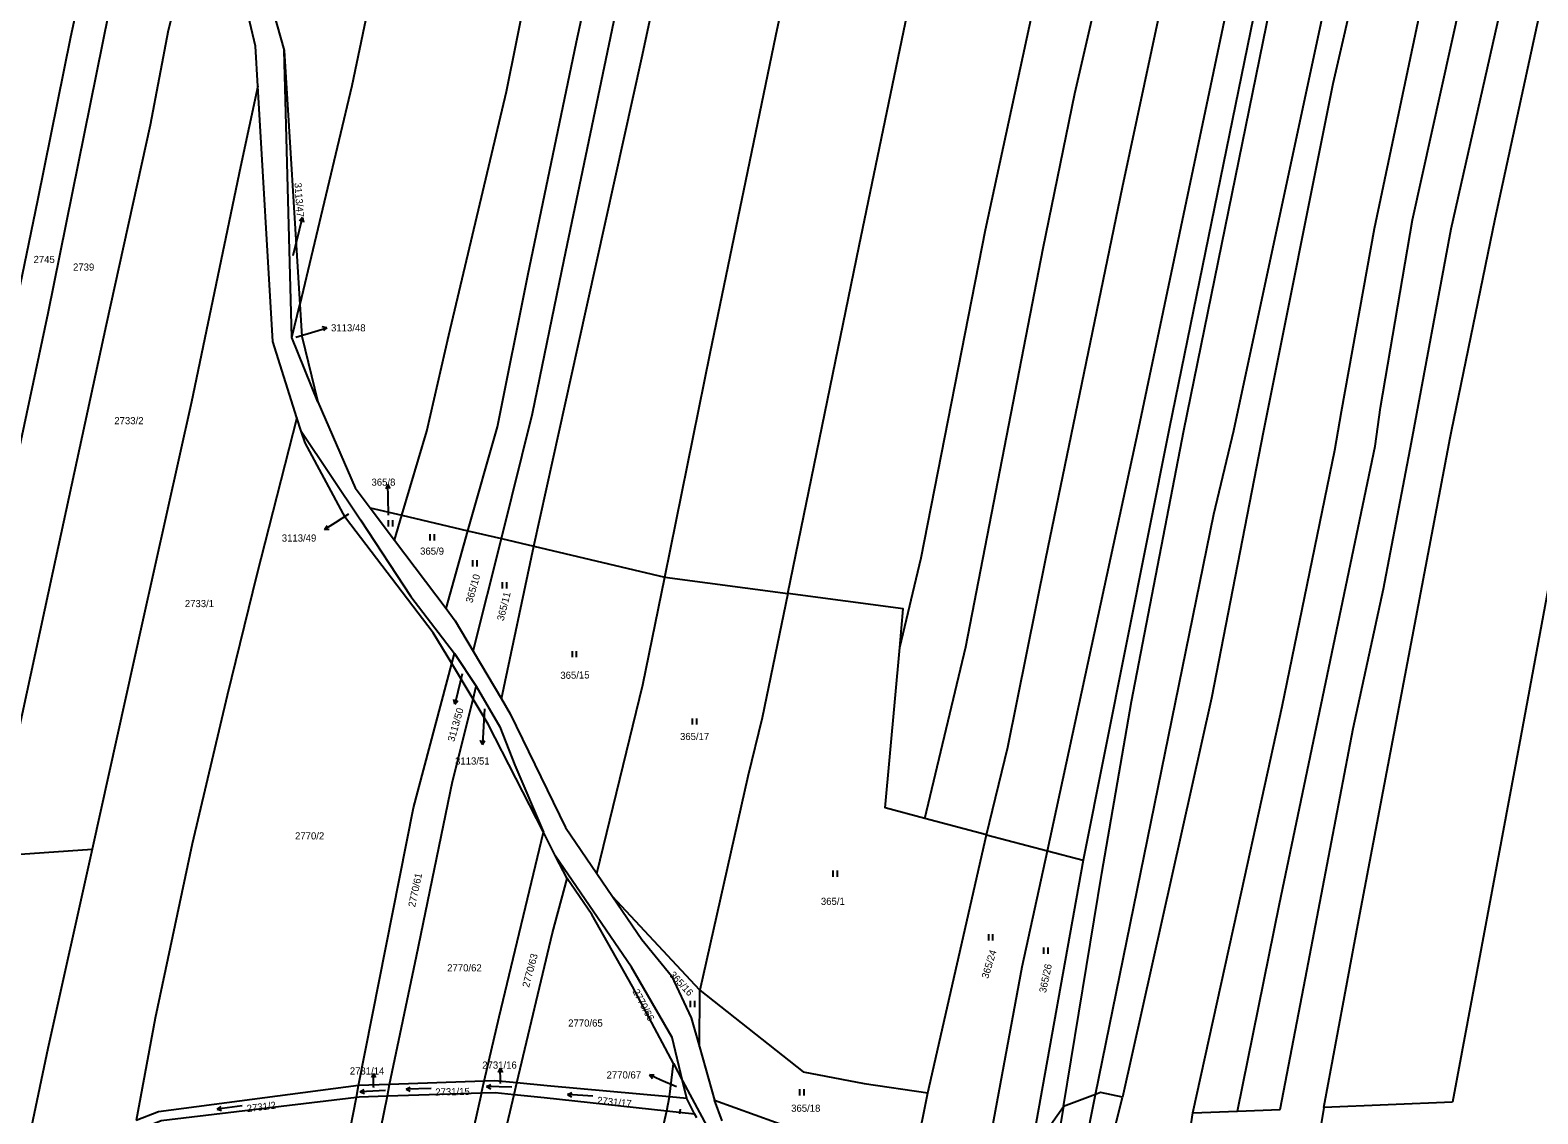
# Model space of a CAD drawing. Extents: x -755528 to -748832, y -1118122 to -1111095.
# Drawn here: x -753634.1 to -753275.1, y -1114927.7 to -1114669.7 of the extents above; entities that cross this region are included whole.
import ezdxf

# ---------------------------------------------------------------- set-up
doc = ezdxf.new("R2010")
doc.units = 0
for name, color, linetype in [('DZ_DO_PUPFL', 7, 'Continuous'), ('DZ_NAD_ZPF', 7, 'Continuous'), ('legenda barvy', 7, 'Continuous'), ('TZ_UMVŽST', 7, 'Continuous')]:
    doc.layers.add(name, color=color, linetype=linetype)

msp = doc.modelspace()

# ---------------------------------------------------------------- linework, layer by layer
at = {"layer": 'DZ_NAD_ZPF'}
for p, q in [((-753577.47, -1114661.02), (-753573.61, -1114674.53)), ((-753571.78, -1114742.92), (-753573.61, -1114674.53)), ((-753573.61, -1114674.53), (-753569.89, -1114734.99)), ((-753571.78, -1114742.92), (-753569.89, -1114734.99)), ((-753565.61, -1114758.21), (-753571.78, -1114742.92)), ((-753569.56, -1114765.17), (-753570.58, -1114761.97)), ((-753553.18, -1114783.41), (-753547.36, -1114791.13)), ((-753553.18, -1114783.41), (-753545.64, -1114785.18)), ((-753547.36, -1114791.13), (-753545.64, -1114785.18)), ((-753545.64, -1114785.18), (-753529.9, -1114788.88)), ((-753535.09, -1114807.4), (-753529.9, -1114788.88)), ((-753529.9, -1114788.88), (-753521.92, -1114790.76)), ((-753547.36, -1114791.13), (-753535.09, -1114807.4)), ((-753528.59, -1114817.59), (-753521.92, -1114790.76)), ((-753521.92, -1114790.76), (-753514.21, -1114792.57)), ((-753521.89, -1114828.92), (-753514.21, -1114792.57)), ((-753514.21, -1114792.57), (-753482.99, -1114799.91)), ((-753482.99, -1114799.91), (-753453.67, -1114803.81)), ((-753528.59, -1114817.59), (-753521.89, -1114828.92)), ((-753533.71, -1114820.53), (-753533.08, -1114818.09)), ((-753528.6, -1114829.01), (-753533.71, -1114820.53)), ((-753533.08, -1114818.09), (-753527.92, -1114825.93)), ((-753528.6, -1114829.01), (-753527.92, -1114825.93)), ((-753509, -1114866.34), (-753511.91, -1114860.63)), ((-753406.39, -1114861.26), (-753421.05, -1114857.37)), ((-753420.37, -1114922.71), (-753406.39, -1114861.26)), ((-753406.39, -1114861.26), (-753391.91, -1114865.1)), ((-753643.43, -1114866.36), (-753619.35, -1114864.71)), ((-753506.27, -1114871.68), (-753509, -1114866.34)), ((-753383.41, -1114867.35), (-753395.87, -1114937.08)), ((-753391.91, -1114865.1), (-753383.41, -1114867.35)), ((-753499.16, -1114870.52), (-753495.47, -1114875.94)), ((-753474.62, -1114898.28), (-753495.47, -1114875.94)), ((-753474.74, -1114911.76), (-753474.62, -1114898.28)), ((-753474.74, -1114911.76), (-753471.13, -1114924.44)), ((-753481.87, -1114923.69), (-753480.96, -1114915.73)), ((-753480.96, -1114915.73), (-753478.76, -1114919.85)), ((-753556.37, -1114923.73), (-753555.92, -1114921.01)), ((-753548.52, -1114920.75), (-753555.92, -1114921.01)), ((-753549.06, -1114923.44), (-753548.52, -1114920.75)), ((-753526.02, -1114919.98), (-753548.52, -1114920.75)), ((-753526.67, -1114922.71), (-753526.02, -1114919.98)), ((-753518.89, -1114923.09), (-753518.24, -1114920.37)), ((-753477.73, -1114924.07), (-753478.76, -1114919.85)), ((-753549.06, -1114923.44), (-753526.67, -1114922.71)), ((-753482.54, -1114926.98), (-753481.87, -1114923.69)), ((-753477.73, -1114924.07), (-753481.87, -1114923.69)), ((-753475.9, -1114927.69), (-753477.73, -1114924.07)), ((-753469.35, -1114929.4), (-753471.13, -1114924.44)), ((-753471.13, -1114924.44), (-753451.81, -1114931.44)), ((-753380.47, -1114923.09), (-753388.04, -1114925.99)), ((-753386.18, -1114952.09), (-753380.47, -1114923.09)), ((-753380.97, -1114951.65), (-753374.05, -1114923.78)), ((-753295.48, -1114924.98), (-753326.11, -1114926.23)), ((-753482.54, -1114926.98), (-753475.9, -1114927.69)), ((-753475.39, -1114928.71), (-753475.9, -1114927.69)), ((-753388.04, -1114925.99), (-753392.57, -1114952.63)), ((-753391.05, -1114930.25), (-753388.04, -1114925.99)), ((-753360.79, -1114949.94), (-753357.27, -1114927.51)), ((-753357.27, -1114927.51), (-753346.62, -1114927.07)), ((-753346.62, -1114927.07), (-753336.49, -1114926.66)), ((-753326.11, -1114926.23), (-753329.47, -1114947.29))]:
    msp.add_line(p, q, dxfattribs=at)
for points in [[(-753391.91, -1114865.1), (-753370.12, -1114764.37), (-753342.59, -1114633.36), (-753322.4, -1114540.31), (-753310.19, -1114487.69), (-753300.09, -1114436.67), (-753286.77, -1114370.72), (-753264.8, -1114264.8), (-753262.01, -1114250.34)], [(-753388.04, -1114925.99), (-753378.91, -1114870.41), (-753371.84, -1114829.51), (-753359.4, -1114765.02), (-753333.11, -1114636.17), (-753306.83, -1114507.39), (-753280.51, -1114378.41), (-753254.07, -1114248.85)], [(-753257.43, -1114249.32), (-753283.85, -1114378.41), (-753310.17, -1114506.98), (-753336.45, -1114635.37), (-753362.83, -1114764.23), (-753383.41, -1114867.35)], [(-753380.47, -1114923.09), (-753352.25, -1114784.92), (-753347.52, -1114765.05), (-753321.73, -1114644.54), (-753301.78, -1114549.55), (-753285.73, -1114476.91), (-753267.23, -1114386.09), (-753258.53, -1114337.83), (-753251.49, -1114312.57), (-753241.68, -1114263.95)], [(-753406.39, -1114861.26), (-753401.29, -1114840.44), (-753392.31, -1114795.48), (-753374.02, -1114707.08), (-753358.06, -1114632.36), (-753344.31, -1114570.05), (-753328.24, -1114502.3), (-753313.96, -1114433.37), (-753295.87, -1114339.69), (-753280.83, -1114267.93)], [(-753235.13, -1114267.34), (-753240.39, -1114297.28), (-753251.09, -1114341.31), (-753268.66, -1114432.14), (-753285.44, -1114506.75), (-753288.02, -1114520.6), (-753301.19, -1114583.62), (-753323.96, -1114682.47), (-753340.43, -1114765.07), (-753352.84, -1114828.76), (-753374.05, -1114923.78)], [(-753357.27, -1114927.51), (-753345.65, -1114874.9), (-753335.97, -1114830.73), (-753323.45, -1114769.69), (-753321.88, -1114760.53), (-753313.99, -1114716.92), (-753301.83, -1114658.93), (-753285.34, -1114585.91), (-753271.38, -1114523.28), (-753269.62, -1114514.13), (-753252.93, -1114437.12), (-753248.23, -1114411.88), (-753236.35, -1114350.91), (-753218.84, -1114274.4)], [(-753421.05, -1114857.37), (-753411.32, -1114816.52), (-753392.9, -1114721.65), (-753385.36, -1114684.8), (-753362.12, -1114584), (-753347.03, -1114516.19), (-753330.1, -1114437.88), (-753316.74, -1114370.96), (-753298.04, -1114276.42)], [(-753346.62, -1114927.07), (-753336.64, -1114877.75), (-753313.83, -1114768.77), (-753312.59, -1114759.54), (-753304.99, -1114714.84), (-753288.84, -1114642.04), (-753280.2, -1114605.8), (-753261.79, -1114523.06), (-753246.79, -1114453.38), (-753233.8, -1114391.88), (-753226.71, -1114348.8), (-753209.38, -1114276.19)], [(-753336.49, -1114926.66), (-753330.42, -1114895.38), (-753319.07, -1114836), (-753311.85, -1114802.69), (-753305.21, -1114767.84), (-753295.75, -1114717.04), (-753281.21, -1114652.59), (-753269.65, -1114602.88), (-753259.3, -1114558.02), (-753248.82, -1114510.17), (-753229.75, -1114419.33), (-753218.76, -1114362.62), (-753210.75, -1114321.87), (-753200.23, -1114277.93)], [(-753482.99, -1114799.91), (-753472.19, -1114746.58), (-753456.54, -1114671.05), (-753443.54, -1114609.86), (-753429.02, -1114541.88), (-753415.04, -1114479.21), (-753399.63, -1114399.72), (-753389.17, -1114347.58), (-753374.92, -1114282.49)], [(-753326.11, -1114926.23), (-753317.74, -1114881.48), (-753296.03, -1114766.74), (-753295.7, -1114765.18), (-753285.26, -1114714.64), (-753270.38, -1114645.75), (-753262.54, -1114613.09), (-753253.99, -1114578.06), (-753242.92, -1114533.2), (-753229.75, -1114467.75), (-753214.48, -1114392.62), (-753201.31, -1114320.15), (-753191.66, -1114279.56)], [(-753427.05, -1114816.67), (-753421.95, -1114795.33), (-753406.63, -1114717.25), (-753393.37, -1114655.82), (-753363.47, -1114523.91), (-753342.5, -1114428.02), (-753332.6, -1114374.47), (-753323.21, -1114331.32), (-753312.67, -1114283.86)], [(-753453.67, -1114803.81), (-753436.75, -1114721.08), (-753422.62, -1114652.89), (-753404.93, -1114571.83), (-753384.78, -1114480.87), (-753376.55, -1114438.8), (-753364.34, -1114375.14), (-753354.33, -1114334.25), (-753342.84, -1114288.62)], [(-753521.92, -1114790.76), (-753514.51, -1114760.97), (-753506.94, -1114724.35), (-753491.12, -1114648.31), (-753472.33, -1114560.66), (-753460.31, -1114505.63), (-753447.2, -1114444.23), (-753434.61, -1114386.82), (-753422.98, -1114329.63), (-753416.75, -1114298.6), (-753415.43, -1114293.38)], [(-753514.21, -1114792.57), (-753503.61, -1114744.79), (-753488.31, -1114675.57), (-753468.49, -1114582.84), (-753445.47, -1114477.34), (-753425.56, -1114377.48), (-753408.97, -1114296.71), (-753408.09, -1114290.87)], [(-753529.9, -1114788.88), (-753522.81, -1114764.12), (-753515.64, -1114728.13), (-753504, -1114672.45), (-753489.29, -1114604.59), (-753479.49, -1114562.47), (-753466.97, -1114506.52), (-753458.84, -1114469.04), (-753446.41, -1114412.13), (-753439.28, -1114374.74), (-753424.14, -1114300.03)], [(-753545.64, -1114785.18), (-753539.64, -1114765.18), (-753534.46, -1114742.36), (-753520.67, -1114684.28), (-753515.99, -1114660.95), (-753492.74, -1114552.19), (-753480.23, -1114495.22), (-753460.74, -1114406.56), (-753455.16, -1114378.63), (-753439.66, -1114301.88)], [(-753477.67, -1114315.36), (-753482.48, -1114340.66), (-753489.85, -1114373.61), (-753501.24, -1114423.4), (-753519.79, -1114507.09), (-753533.42, -1114568.36), (-753549.84, -1114646.02), (-753557.48, -1114682.99), (-753569.89, -1114734.99)], [(-753610.25, -1114606.01), (-753617.12, -1114637.26), (-753624.49, -1114671.37), (-753632.34, -1114710.29), (-753639.7, -1114745.63), (-753646.59, -1114780.5), (-753654.58, -1114817.91), (-753663.71, -1114856.29), (-753671.41, -1114887.98), (-753679.86, -1114921.84)], [(-753604.79, -1114614.61), (-753613.99, -1114658.59), (-753629.87, -1114737.18), (-753640.64, -1114787.58), (-753650.44, -1114834.53), (-753663.46, -1114889.5), (-753671.97, -1114923.35)], [(-753592.96, -1114636.98), (-753601.26, -1114669.82), (-753605.55, -1114692.31), (-753616.04, -1114739.83), (-753628.68, -1114798.6), (-753643.43, -1114866.36)], [(-753579.89, -1114683.06), (-753580.44, -1114673.52), (-753583.19, -1114661.99), (-753589.7, -1114643.54), (-753592.96, -1114636.98)], [(-753579.89, -1114683.06), (-753584.03, -1114702.28), (-753595.68, -1114758.18), (-753607.42, -1114810.88), (-753619.35, -1114864.71)], [(-753570.58, -1114761.97), (-753576.36, -1114743.83), (-753579.89, -1114683.06)], [(-753569.89, -1114734.99), (-753569.42, -1114742.6), (-753565.61, -1114758.21)], [(-753565.61, -1114758.21), (-753556.7, -1114778.7), (-753553.18, -1114783.41)], [(-753570.58, -1114761.97), (-753580.11, -1114799.28), (-753587.21, -1114828.12), (-753595.54, -1114863.4), (-753604.34, -1114904.93), (-753608.87, -1114929.33)], [(-753533.71, -1114820.53), (-753538.12, -1114813.2), (-753559, -1114785.81), (-753568.66, -1114767.99), (-753569.56, -1114765.17)], [(-753569.56, -1114765.17), (-753555.44, -1114786.3), (-753543.49, -1114804.51), (-753533.08, -1114818.09)], [(-753265.56, -1114765.37), (-753267.16, -1114773.07), (-753279.16, -1114837.78), (-753295.48, -1114924.98)], [(-753499.16, -1114870.52), (-753488.21, -1114825.61), (-753482.99, -1114799.91)], [(-753453.67, -1114803.81), (-753459.79, -1114833.45), (-753463.25, -1114847.41), (-753474.62, -1114898.28)], [(-753427.05, -1114816.67), (-753426.22, -1114807.46), (-753453.67, -1114803.81)], [(-753535.09, -1114807.4), (-753532.88, -1114810.33), (-753528.59, -1114817.59)], [(-753421.05, -1114857.37), (-753430.49, -1114854.86), (-753427.05, -1114816.67)], [(-753555.92, -1114921.01), (-753542.87, -1114854.9), (-753533.71, -1114820.53)], [(-753527.92, -1114825.93), (-753522.24, -1114835.6), (-753518.74, -1114844.67), (-753511.91, -1114860.63)], [(-753548.52, -1114920.75), (-753542.13, -1114890.19), (-753533.55, -1114848.56), (-753528.6, -1114829.01)], [(-753511.91, -1114860.63), (-753525.05, -1114834.91), (-753528.6, -1114829.01)], [(-753521.89, -1114828.92), (-753519.79, -1114832.48), (-753506.65, -1114859.53), (-753499.16, -1114870.52)], [(-753526.02, -1114919.98), (-753522.41, -1114904.64), (-753511.91, -1114860.63)], [(-753619.35, -1114864.71), (-753629.9, -1114912.16), (-753637.4, -1114947.63)], [(-753478.76, -1114919.85), (-753481.26, -1114909.56), (-753490.91, -1114892.84), (-753509, -1114866.34)], [(-753408.1, -1114946.81), (-753405.08, -1114931.27), (-753397.93, -1114892.69), (-753391.91, -1114865.1)], [(-753518.24, -1114920.37), (-753509.77, -1114884.59), (-753506.27, -1114871.68)], [(-753480.96, -1114915.73), (-753490.68, -1114897.4), (-753500.41, -1114880.23), (-753506.27, -1114871.68)], [(-753495.47, -1114875.94), (-753488.46, -1114886.21), (-753481.4, -1114894.9), (-753476.69, -1114904.88), (-753474.74, -1114911.76)], [(-753474.62, -1114898.28), (-753450.03, -1114917.75), (-753435.5, -1114920.48), (-753420.37, -1114922.71)], [(-753555.92, -1114921.01), (-753603.56, -1114927.22), (-753608.87, -1114929.33)], [(-753518.24, -1114920.37), (-753523.47, -1114919.89), (-753526.02, -1114919.98)], [(-753481.87, -1114923.69), (-753511, -1114921.03), (-753518.24, -1114920.37)], [(-753478.76, -1114919.85), (-753464.35, -1114946.78), (-753455.56, -1114955.73), (-753442.66, -1114964.55), (-753428.65, -1114973.62)], [(-753609.34, -1114931.95), (-753602.95, -1114929.29), (-753556.37, -1114923.73)], [(-753565.08, -1114965.41), (-753559.31, -1114938.75), (-753556.37, -1114923.73)], [(-753556.37, -1114923.73), (-753555.77, -1114923.66), (-753549.06, -1114923.44)], [(-753526.67, -1114922.71), (-753531.52, -1114944.33), (-753537.73, -1114940.93), (-753545.43, -1114939.1), (-753552.22, -1114939), (-753549.06, -1114923.44)], [(-753535.34, -1115001.75), (-753526.62, -1114958.48), (-753525.15, -1114949.67), (-753518.89, -1114923.09)], [(-753526.67, -1114922.71), (-753523.41, -1114922.61), (-753518.89, -1114923.09)], [(-753518.89, -1114923.09), (-753511.72, -1114923.86), (-753482.54, -1114926.98)], [(-753423.93, -1114941.39), (-753423.03, -1114936.17), (-753420.37, -1114922.71)], [(-753374.05, -1114923.78), (-753379.25, -1114922.62), (-753380.47, -1114923.09)], [(-753499.33, -1115003.37), (-753488.94, -1114957.99), (-753486.22, -1114943.26), (-753482.54, -1114926.98)]]:
    msp.add_lwpolyline(points, dxfattribs=at)
at = {"layer": 'legenda barvy'}
for p, q in [((-753569.274, -1114714.338), (-753570.002, -1114715.189)), ((-753570, -1114717.25), (-753569.274, -1114714.338)), ((-753569.274, -1114714.338), (-753569.03, -1114715.431)), ((-753571.47, -1114723.35), (-753570, -1114717.25)), ((-753570.82, -1114742.77), (-753566.35, -1114741.44)), ((-753566.35, -1114741.44), (-753563.48, -1114740.563)), ((-753563.48, -1114740.563), (-753564.584, -1114740.377)), ((-753563.48, -1114740.563), (-753564.291, -1114741.334)), ((-753548.985, -1114777.891), (-753549.45, -1114778.909)), ((-753548.88, -1114780.89), (-753548.985, -1114777.891)), ((-753548.985, -1114777.891), (-753548.449, -1114778.874)), ((-753548.75, -1114785.18), (-753548.88, -1114780.89)), ((-753558.35, -1114784.96), (-753561.48, -1114787)), ((-753561.48, -1114787), (-753563.997, -1114788.634)), ((-753563.997, -1114788.634), (-753563.43, -1114787.669)), ((-753563.997, -1114788.634), (-753562.884, -1114788.509)), ((-753531.24, -1114823), (-753532.28, -1114827.24)), ((-753532.28, -1114827.24), (-753533.006, -1114830.152)), ((-753533.006, -1114830.152), (-753533.25, -1114829.059)), ((-753533.006, -1114830.152), (-753532.278, -1114829.301)), ((-753525.95, -1114831.28), (-753526.27, -1114836.82)), ((-753526.427, -1114839.817), (-753526.875, -1114838.791)), ((-753526.27, -1114836.82), (-753526.427, -1114839.817)), ((-753526.427, -1114839.817), (-753525.875, -1114838.843)), ((-753552.372, -1114918.099), (-753552.856, -1114919.11)), ((-753552.32, -1114921.1), (-753552.372, -1114918.099)), ((-753552.372, -1114918.099), (-753551.854, -1114919.092)), ((-753522.172, -1114916.859), (-753522.656, -1114917.87)), ((-753522.12, -1114919.86), (-753522.172, -1114916.859)), ((-753522.172, -1114916.859), (-753521.654, -1114917.852)), ((-753552.31, -1114921.55), (-753552.32, -1114921.1)), ((-753522.11, -1114920.52), (-753522.12, -1114919.86)), ((-753486.662, -1114918.449), (-753485.543, -1114918.399)), ((-753483.92, -1114919.67), (-753486.662, -1114918.449)), ((-753486.662, -1114918.449), (-753485.95, -1114919.314)), ((-753480.18, -1114921.32), (-753483.92, -1114919.67)), ((-753479.33, -1114926.6), (-753479.48, -1114927.76))]:
    msp.add_line(p, q, dxfattribs=at)
at = {"layer": 'TZ_UMVŽST'}
for p, q in [((-753548.781, -1114787.87), (-753548.781, -1114786.37)), ((-753547.78, -1114787.87), (-753547.78, -1114786.37)), ((-753538.871, -1114791.24), (-753538.871, -1114789.74)), ((-753537.87, -1114791.24), (-753537.87, -1114789.74)), ((-753528.681, -1114797.38), (-753528.681, -1114795.88)), ((-753527.68, -1114797.38), (-753527.68, -1114795.88)), ((-753521.651, -1114802.61), (-753521.651, -1114801.11)), ((-753520.65, -1114802.61), (-753520.65, -1114801.11)), ((-753505.011, -1114819.03), (-753505.011, -1114817.53)), ((-753504.01, -1114819.03), (-753504.01, -1114817.53)), ((-753476.381, -1114835.06), (-753476.381, -1114833.56)), ((-753475.38, -1114835.06), (-753475.38, -1114833.56)), ((-753442.881, -1114871.3), (-753442.881, -1114869.8)), ((-753441.88, -1114871.3), (-753441.88, -1114869.8)), ((-753405.861, -1114886.43), (-753405.861, -1114884.93)), ((-753404.86, -1114886.43), (-753404.86, -1114884.93)), ((-753392.741, -1114889.62), (-753392.741, -1114888.12)), ((-753391.74, -1114889.62), (-753391.74, -1114888.12)), ((-753476.841, -1114902.33), (-753476.841, -1114900.83)), ((-753475.84, -1114902.33), (-753475.84, -1114900.83)), ((-753544.606, -1114921.887), (-753543.647, -1114921.352)), ((-753538.609, -1114921.677), (-753544.606, -1114921.887)), ((-753525.427, -1114921.239), (-753524.441, -1114920.754)), ((-753519.427, -1114921.343), (-753525.427, -1114921.239)), ((-753525.427, -1114921.239), (-753524.458, -1114921.757)), ((-753555.523, -1114922.449), (-753554.574, -1114921.897)), ((-753549.532, -1114922.135), (-753555.523, -1114922.449)), ((-753555.523, -1114922.449), (-753554.521, -1114922.899)), ((-753544.606, -1114921.887), (-753543.612, -1114922.354)), ((-753506.149, -1114923.101), (-753505.139, -1114922.669)), ((-753500.164, -1114923.52), (-753506.149, -1114923.101)), ((-753506.149, -1114923.101), (-753505.209, -1114923.669)), ((-753450.811, -1114923.35), (-753450.811, -1114921.85)), ((-753449.81, -1114923.35), (-753449.81, -1114921.85)), ((-753583.61, -1114925.848), (-753589.566, -1114926.579)), ((-753589.566, -1114926.579), (-753588.657, -1114925.962)), ((-753589.566, -1114926.579), (-753588.535, -1114926.958))]:
    msp.add_line(p, q, dxfattribs=at)

# ---------------------------------------------------------------- texts
at = {"layer": 'DZ_DO_PUPFL'}
for s, rotation, p in [('3113/47', 274, (-753571.188, -1114706.083)), ('365/10', 74, (-753528.832, -1114806.204)), ('365/11', 76, (-753521.365, -1114810.465)), ('365/15', 1, (-753507.855, -1114824.179)), ('3113/50', 74, (-753533.139, -1114839.263)), ('2770/61', 78, (-753542.468, -1114878.626)), ('365/24', 73, (-753406.007, -1114895.658)), ('2770/63', 75, (-753515.338, -1114897.769)), ('365/26', 78, (-753392.258, -1114899.026)), ('365/16', 313, (-753482.041, -1114894.759)), ('2770/66', 298, (-753490.74, -1114898.569)), ('2731/15', 1, (-753537.635, -1114923.369)), ('2731/2', 7, (-753582.416, -1114927.313)), ('2731/17', 354, (-753499.168, -1114925.315))]:
    msp.add_text(s, height=1.7, rotation=rotation, dxfattribs=at).set_placement(p)
for s, p in [('2745', (-753633.3, -1114725.15)), ('2739', (-753623.9, -1114726.96)), ('3113/48', (-753562.47, -1114741.43)), ('2733/2', (-753614.07, -1114763.53)), ('365/8', (-753552.837, -1114778.17)), ('3113/49', (-753574.193, -1114791.478)), ('365/9', (-753541.26, -1114794.59)), ('2733/1', (-753597.28, -1114807.08)), ('365/17', (-753479.38, -1114838.73)), ('3113/51', (-753532.933, -1114844.568)), ('2770/2', (-753571.04, -1114862.39)), ('365/1', (-753445.83, -1114877.97)), ('2770/62', (-753534.81, -1114893.81)), ('2770/65', (-753506, -1114906.95)), ('2731/14', (-753557.993, -1114918.36)), ('2731/16', (-753526.463, -1114916.96)), ('2770/67', (-753496.863, -1114919.31)), ('365/18', (-753452.91, -1114927.23))]:
    msp.add_text(s, height=1.7, dxfattribs=at).set_placement(p)

doc.saveas('drawing.dxf')
